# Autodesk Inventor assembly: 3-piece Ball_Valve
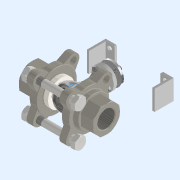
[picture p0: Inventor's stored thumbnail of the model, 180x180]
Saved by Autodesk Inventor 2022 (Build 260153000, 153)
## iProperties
Created: 2015-07
Part Number: 3-piece Ball_Valve
Description: STEP AP214
Document SubType Name: Assembly
Designer: admin
Sending System: PARTsolutions
Title: G:/3-piece Ball_Valve.stp
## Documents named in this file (31)
- C:\Users\admin\Desktop\inventor\vslvola_proporzionale\3-piece Ball_Valve.iam
- C:\Users\admin\Desktop\inventor\vslvola_proporzionale\_DN10  Packing.ipt
- C:\Users\admin\Desktop\inventor\vslvola_proporzionale\_DN10  Packing_1.ipt
- C:\Users\admin\Desktop\inventor\vslvola_proporzionale\_DN10  Packing_2.ipt
- C:\Users\admin\Desktop\inventor\vslvola_proporzionale\_DN10  Packing_7.ipt
- C:\Users\admin\Desktop\inventor\vslvola_proporzionale\_DN10  Packing_8.ipt
- C:\Users\admin\Desktop\inventor\vslvola_proporzionale\_DN10  Packing_9.ipt
- C:\Users\admin\Desktop\inventor\vslvola_proporzionale\_DN10  Packing_10.ipt
- C:\Users\admin\Desktop\inventor\vslvola_proporzionale\_DN10  Packing_11.ipt
- C:\Users\admin\Desktop\inventor\vslvola_proporzionale\_DN10  Packing_12.ipt
- C:\Users\admin\Desktop\inventor\vslvola_proporzionale\_DN10  Packing_13.ipt
- C:\Users\admin\Desktop\inventor\vslvola_proporzionale\_DN10  Packing_14.ipt
- C:\Users\admin\Desktop\inventor\vslvola_proporzionale\_DN10  Packing_15.ipt
- C:\Users\admin\Desktop\inventor\vslvola_proporzionale\_DN10  Packing_16.ipt
- C:\Users\admin\Desktop\inventor\vslvola_proporzionale\_DN10  Packing_17.ipt
- C:\Users\admin\Desktop\inventor\vslvola_proporzionale\_DN10  Packing_18.ipt
- C:\Users\admin\Desktop\inventor\vslvola_proporzionale\_DN10  Packing_19.ipt
- C:\Users\admin\Desktop\inventor\vslvola_proporzionale\_DN10  Packing_20.ipt
- C:\Users\admin\Desktop\inventor\vslvola_proporzionale\_DN10  Packing_21.ipt
- C:\Users\admin\Desktop\inventor\vslvola_proporzionale\_DN10  Packing_22.ipt
- C:\Users\admin\Desktop\inventor\vslvola_proporzionale\_DN10  Packing_23.ipt
- C:\Users\admin\Desktop\inventor\vslvola_proporzionale\_DN10  Packing_24.ipt
- C:\Users\admin\Desktop\inventor\vslvola_proporzionale\_DN10  Packing_25.ipt
- C:\Users\admin\Desktop\inventor\vslvola_proporzionale\Servo_20kg.ipt
- C:\Users\admin\Desktop\inventor\vslvola_proporzionale\disco.mg995.Al.ipt
- C:\Users\admin\Desktop\inventor\vslvola_proporzionale\blocco_perno_sfera.ipt
- C:\Users\admin\Desktop\inventor\vslvola_proporzionale\blocco_perno.ipt
- C:\Users\admin\Documents\Inventor\Content Center Files\R2022\it-IT\AS 1112 (4)\AS 1112 - M6(2).ipt
- C:\Users\admin\Documents\Inventor\Content Center Files\R2022\it-IT\AS 1110\AS 1110 - M2 x 12.ipt
- C:\Users\admin\Documents\Inventor\Content Center Files\R2022\it-IT\AS 1112 (2)\AS 1112 - M2,5  Tipo 5.ipt
- C:\Users\admin\Desktop\inventor\vslvola_proporzionale\blocco_servo.ipt
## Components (36 placed, 30 different names)
1. _DN10  Packing — Coincidente:14, Coincidente:15, Coincidente:17, Coincidente:21
2. _DN10  Packing_1 — Coincidente:15, Coincidente:16, Coincidente:21
3. _DN10  Packing_2 — Coincidente:14, Coincidente:17, Coincidente:18
4. _DN10  Packing_7 — Coincidente:16, Coincidente:18, Coincidente:19, Coincidente:20, Angolo:1, Coincidente:22, Allineato:3, Coincidente:23, Coincidente:24, Coincidente:25, Angolo:3, Angolo:4, Coincidente:27, Angolo:5
5. _DN10  Packing_8 — Coincidente:2, Allineato:2, Coincidente:3, Coincidente:19, Coincidente:20, Angolo:1
6. _DN10  Packing_9 — Rotazionale:1
7. _DN10  Packing_10 — Coincidente:1, Allineato:1
8. _DN10  Packing_11 — Rotazionale:10
9. _DN10  Packing_12 — Rotazionale:11
10. _DN10  Packing_13 — Rotazionale:13
11. _DN10  Packing_14 — Rotazionale:12
12. _DN10  Packing_15 — Rotazionale:7, Rotazionale:11
13. _DN10  Packing_16 — Rotazionale:6, Rotazionale:10
14. _DN10  Packing_17 — Rotazionale:9, Rotazionale:13
15. _DN10  Packing_18 — Rotazionale:8, Rotazionale:12
16. _DN10  Packing_19 — Coincidente:6, Coincidente:7, Coincidente:9, Rotazionale:6, Rotazionale:7, Rotazionale:8, Rotazionale:9
17. _DN10  Packing_20 — Coincidente:11, Rotazionale:2
18. _DN10  Packing_21 — Coincidente:13, Rotazionale:5
19. _DN10  Packing_22 — Coincidente:12, Rotazionale:4
20. _DN10  Packing_23 — Coincidente:10, Rotazionale:3
21. _DN10  Packing_24 — Coincidente:4, Coincidente:5, Coincidente:8, Coincidente:10, Coincidente:11, Coincidente:12, Coincidente:13, Rotazionale:2, Rotazionale:3, Rotazionale:4, Rotazionale:5
22. _DN10  Packing_25 — Coincidente:1, Allineato:1, Coincidente:2, Allineato:2, Coincidente:3, Rotazionale:1, Coincidente:4, Coincidente:5, Coincidente:6, Coincidente:7, Coincidente:8, Coincidente:9, Angolo:2, Angolo:3
23. Servo_20kg:1 — Coincidente:22, Angolo:2, Rotazionale:14, Allineato:4
24. disco.mg995.Al:1 — Rotazionale:14, Coincidente:25, Angolo:4, Coincidente:26
25. blocco_perno_sfera:1 — Allineato:3, Coincidente:26
26. blocco_perno:1 — Coincidente:23, Coincidente:24, Coincidente:27, Coincidente:29
27. AS 1112 (4) - Metrico M6:1 — Angolo:5
28. AS 1110 - Metrico M2 x 12:1
29. AS 1110 - Metrico M2 x 12:2
30. AS 1110 - Metrico M2 x 12:3
31. AS 1110 - Metrico M2 x 12:4
32. AS 1112 (2) - Metrico M2,5  Tipo 5:5 — Coincidente:29
33. AS 1112 (2) - Metrico M2,5  Tipo 5:1
34. AS 1112 (2) - Metrico M2,5  Tipo 5:2
35. AS 1112 (2) - Metrico M2,5  Tipo 5:4
36. blocco_servo:1 — Allineato:4
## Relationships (51: Mate 28, RevoluteJoint 14, Angle 5, Flush 4)
- Coincidente:1 [Mate]: _DN10  Packing_10 ↔ _DN10  Packing_25
- Allineato:1 [Flush]: _DN10  Packing_10 ↔ _DN10  Packing_25
- Coincidente:2 [Mate]: _DN10  Packing_8 ↔ _DN10  Packing_25
- Allineato:2 [Flush]: _DN10  Packing_8 ↔ _DN10  Packing_25
- Coincidente:3 [Mate]: _DN10  Packing_8 ↔ _DN10  Packing_25
- Rotazionale:1 [RevoluteJoint]: _DN10  Packing_9 ↔ _DN10  Packing_25
- Coincidente:4 [Mate]: _DN10  Packing_24 ↔ _DN10  Packing_25
- Coincidente:5 [Mate]: _DN10  Packing_24 ↔ _DN10  Packing_25
- Coincidente:6 [Mate]: _DN10  Packing_19 ↔ _DN10  Packing_25
- Coincidente:7 [Mate]: _DN10  Packing_19 ↔ _DN10  Packing_25
- Coincidente:8 [Mate]: _DN10  Packing_24 ↔ _DN10  Packing_25
- Coincidente:9 [Mate]: _DN10  Packing_19 ↔ _DN10  Packing_25
- Coincidente:10 [Mate]: _DN10  Packing_23 ↔ _DN10  Packing_24
- Coincidente:11 [Mate]: _DN10  Packing_20 ↔ _DN10  Packing_24
- Coincidente:12 [Mate]: _DN10  Packing_22 ↔ _DN10  Packing_24
- Coincidente:13 [Mate]: _DN10  Packing_21 ↔ _DN10  Packing_24
- Coincidente:14 [Mate]: _DN10  Packing ↔ _DN10  Packing_2
- Coincidente:15 [Mate]: _DN10  Packing ↔ _DN10  Packing_1
- Coincidente:16 [Mate]: _DN10  Packing_1 ↔ _DN10  Packing_7
- Coincidente:17 [Mate]: _DN10  Packing ↔ _DN10  Packing_2
- Coincidente:18 [Mate]: _DN10  Packing_2 ↔ _DN10  Packing_7
- Coincidente:19 [Mate]: _DN10  Packing_7 ↔ _DN10  Packing_8
- Coincidente:20 [Mate]: _DN10  Packing_7 ↔ _DN10  Packing_8
- Rotazionale:2 [RevoluteJoint]: _DN10  Packing_20 ↔ _DN10  Packing_24
- Rotazionale:3 [RevoluteJoint]: _DN10  Packing_23 ↔ _DN10  Packing_24
- Rotazionale:4 [RevoluteJoint]: _DN10  Packing_22 ↔ _DN10  Packing_24
- Rotazionale:5 [RevoluteJoint]: _DN10  Packing_21 ↔ _DN10  Packing_24
- Rotazionale:6 [RevoluteJoint]: _DN10  Packing_16 ↔ _DN10  Packing_19
- Rotazionale:7 [RevoluteJoint]: _DN10  Packing_15 ↔ _DN10  Packing_19
- Rotazionale:8 [RevoluteJoint]: _DN10  Packing_18 ↔ _DN10  Packing_19
- Rotazionale:9 [RevoluteJoint]: _DN10  Packing_17 ↔ _DN10  Packing_19
- Rotazionale:10 [RevoluteJoint]: _DN10  Packing_11 ↔ _DN10  Packing_16
- Rotazionale:11 [RevoluteJoint]: _DN10  Packing_12 ↔ _DN10  Packing_15
- Rotazionale:12 [RevoluteJoint]: _DN10  Packing_14 ↔ _DN10  Packing_18
- Rotazionale:13 [RevoluteJoint]: _DN10  Packing_13 ↔ _DN10  Packing_17
- Coincidente:21 [Mate]: _DN10  Packing ↔ _DN10  Packing_1
- Angolo:1 [Angle]: _DN10  Packing_7 ↔ _DN10  Packing_8
- Coincidente:22 [Mate]: _DN10  Packing_7 ↔ Servo_20kg:1
- Angolo:2 [Angle]: _DN10  Packing_25 ↔ Servo_20kg:1
- Rotazionale:14 [RevoluteJoint]: Servo_20kg:1 ↔ disco.mg995.Al:1
- Allineato:3 [Flush]: _DN10  Packing_7 ↔ blocco_perno_sfera:1
- Coincidente:23 [Mate]: _DN10  Packing_7 ↔ blocco_perno:1
- Coincidente:24 [Mate]: _DN10  Packing_7 ↔ blocco_perno:1
- Coincidente:25 [Mate]: _DN10  Packing_7 ↔ disco.mg995.Al:1
- Angolo:3 [Angle]: _DN10  Packing_7 ↔ _DN10  Packing_25
- Angolo:4 [Angle]: _DN10  Packing_7 ↔ disco.mg995.Al:1
- Coincidente:26 [Mate]: disco.mg995.Al:1 ↔ blocco_perno_sfera:1
- Coincidente:27 [Mate]: _DN10  Packing_7 ↔ blocco_perno:1
- Coincidente:29 [Mate]: blocco_perno:1 ↔ AS 1112 (2) - Metrico M2,5  Tipo 5:5
- Angolo:5 [Angle]: _DN10  Packing_7 ↔ AS 1112 (4) - Metrico M6:1
- Allineato:4 [Flush]: Servo_20kg:1 ↔ blocco_servo:1
